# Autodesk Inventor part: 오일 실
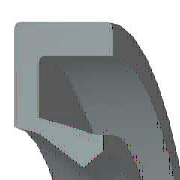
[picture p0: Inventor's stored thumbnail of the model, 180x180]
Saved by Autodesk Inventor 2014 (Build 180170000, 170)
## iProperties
IsCustomPart: 1
Created: 2012-02
Part Number: 오일 실
Material: 고무
Description: 오일 실 - 스프링 장착, 비스프링, 고무 덮개 G
Document SubType Name: Modeling
Standard: JIS B 2402
Designer: mduedu
Standards Organization: JIS
Language: ko-KR
Size Designation: 20 32 5 A
Categories: <MemberInstance><Categories><Category DisplayName="샤프트 부품" InternalName="7f7aeb1f-a693-4053-b835-cee3144e0d98" Mnemonic="SHFT"><Category DisplayName="실링" Intern
Density: 0.93 g/cm^3
Appearance: 고무 - 검은색 - 버전 1.1
Author: mduedu
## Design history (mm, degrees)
body "Solid1"
revolve "회전1" stored, may be unused: angle "d29" = 360 deg
chamfer "모따기1" distance "d30" = 0.25 (= 0.05 x b); stored, may be unused: second distance "d31" = 0.5 (= 0.1 x b), angle "d39" = 45 deg
chamfer "모따기2" distance "d32" = 0.5 (= 0.1 x b); stored, may be unused: second distance "d33" = 0.25 (= 0.05 x b), angle "d40" = 45 deg
fillet "모깎기1" dims "d34" = 0.25 (= 0.05 x b)
sketch "스케치2"
  geometry: L1 (10.997, -3.438)-(11.297, -5); L2 (10.597, -3.282)-(10.997, -3.438); L3 (10, -1.72)-(10.597, -3.282); L4 (11.091, -1.22)-(10, -1.72); L5 (12.133, -3.75)-(11.091, -1.22); L6 (13.333, -3.75)-(12.133, -3.75); L7 (14.667, -1.25)-(13.333, -3.75); L8 (14.667, 0)-(14.667, -1.25); L9 (16, 0)-(14.667, 0); L10 (16, -5)-(16, 0); L11 (11.297, -5)-(16, -5); L12 (0, -9.6)-(0, 1.6) reference; L13 (28, 0)-(14, 0) reference
  constraints: 22 end point, 3 horizontal, 2 vertical
  dimensions: "d2" = 5 distance of L10.start L9.start (= b); "d4" = 1.25 vertical distance of L5.start L1.end (= 0.25 x b); "d6" = 1.33333 distance of L9.start L8.start (= 0.111111 x dd - 0.111111 x Diam); "d8" = 1.25 distance of L8.start L7.start (= 0.25 x b); "d10" = 1.33333 horizontal distance of L7.start L6.start (= 0.111111 x dd - 0.111111 x Diam); "d12" = 1.21951 vertical distance of L9.start L4.start (= 0.243902 x b); "d14" = 1.09091 horizontal distance of L4.start L3.start (= 0.0909091 x dd - 0.0909091 x Diam); "d16" = 0.5 vertical distance of L4.start L3.start (= 0.1 x b); "d18" = 1.2 distance of L6.start L5.start (= 0.1 x dd - 0.1 x Diam); "d20" = 1.5625 vertical distance of L3.start L2.start (= 0.3125 x b); "d22" = 0.59701 horizontal distance of L3.start L2.start (= 0.0497512 x dd - 0.0497512 x Diam); "d24" = 0.3 horizontal distance of L1.start L1.end (= 0.025 x dd - 0.025 x Diam); "d26" = 1.5625 vertical distance of L1.start L1.end (= 0.3125 x b); "d28" = 0.4 horizontal distance of L2.start L1.start (= 0.0333333 x dd - 0.0333333 x Diam); "d35" = 0 distance between parallel lines of L13 L9; "d36" = 16 distance between parallel lines of L12 L10 (= 0.5 x dd); "d37" = 10 distance from line of L12 L3.start (= 0.5 x Diam)
other parameters: "dd" = 32 [user parameter; used in 8 equation terms], "b" = 5 [user parameter; used in 12 equation terms], "d1" = 8 (derived), "d3" = 2 (derived), "d5" = 2.22222 (derived), "d7" = 2 (derived), "d9" = 2.22222 (derived), "d11" = 1.95122 (derived), "d13" = 1.81818 (derived), "d15" = 0.8 (derived), "d17" = 2 (derived), "d19" = 2.5 (derived), "d21" = 0.99502 (derived), "d23" = 0.5 (derived), "d25" = 2.5 (derived), "d27" = 0.66667 (derived), "d38" = 0
